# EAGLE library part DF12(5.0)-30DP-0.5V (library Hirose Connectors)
Connector, Header, board-board, 30-pin. Dual Row, 5mm stack height, 0.5mm Pitch (Hirose)
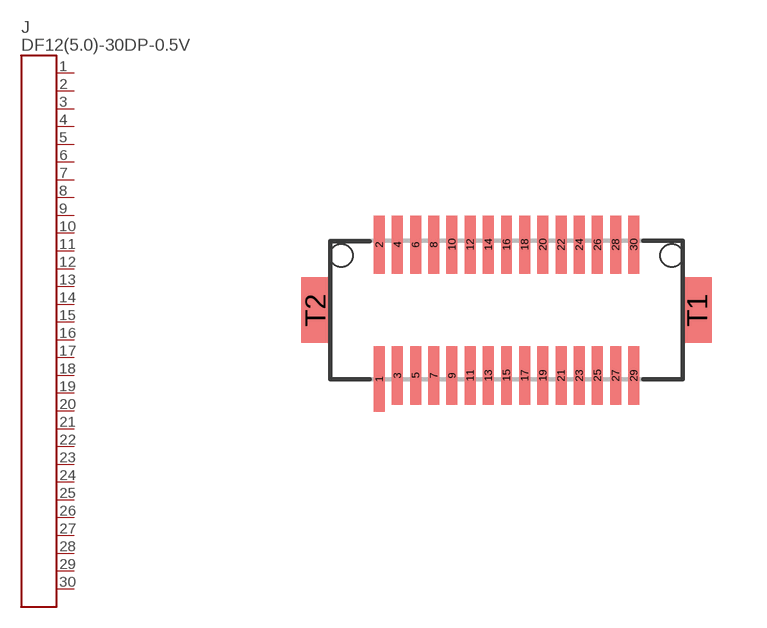
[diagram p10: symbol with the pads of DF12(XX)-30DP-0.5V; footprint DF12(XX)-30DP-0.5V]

Designator prefix J

## DF12(5.0)-30DP-0.5V  [DF12(XX)-30DP-0.5V]
1  P$1
2  P$2
3  P$3
4  P$4
5  P$5
6  P$6
7  P$7
8  P$8
9  P$9
10  P$10
11  P$11
12  P$12
13  P$13
14  P$14
15  P$15
16  P$16
17  P$17
18  P$18
19  P$19
20  P$20
21  P$21
22  P$22
23  P$23
24  P$24
25  P$25
26  P$26
27  P$27
28  P$28
29  P$29
30  P$30

## Footprint DF12(XX)-30DP-0.5V (pad centres in mm)
smd 0.3 x 1.8: 1 -3.5,-1.9
smd 0.3 x 1.6: 2 -3.5,1.8; 3 -3,-1.8; 4 -3,1.8; 5 -2.5,-1.8; 6 -2.5,1.8; 7 -2,-1.8; 8 -2,1.8; 9 -1.5,-1.8; 10 -1.5,1.8; 11 -1,-1.8; 12 -1,1.8; 13 -0.5,-1.8; 14 -0.5,1.8; 15 0,-1.8; 16 0,1.8; 17 0.5,-1.8; 18 0.5,1.8; 19 1,-1.8; 20 1,1.8; 21 1.5,-1.8; 22 1.5,1.8; 23 2,-1.8; 24 2,1.8; 25 2.5,-1.8; 26 2.5,1.8; 27 3,-1.8; 28 3,1.8; 29 3.5,-1.8; 30 3.5,1.8
smd 0.8 x 1.8: T1 5.25,0; T2 -5.25,0
hole 0.635 at -4.55,1.5
hole 0.635 at 4.55,1.5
